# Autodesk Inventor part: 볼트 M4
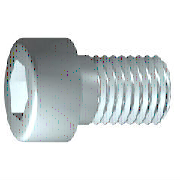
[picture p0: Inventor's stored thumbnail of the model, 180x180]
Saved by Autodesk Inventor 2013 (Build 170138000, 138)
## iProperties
IsCustomPart: 1
Created: 2015-10
Part Number: 볼트 M4
Material: 강, 연강
Description: 6각머리 태핑 나사
Document SubType Name: Modeling
Standard: KS B 1003
Designer: mdu
Standards Organization: KS
Language: ko-KR
Size Designation: M 4 x 16
Categories: <MemberInstance><Categories><Category DisplayName="조임쇠" InternalName="e4da775c-781d-43d5-af7c-5136215cf5a6" Mnemonic="FSTN"><Category DisplayName="볼트" InternalN
Density: 7.86 g/cm^3
Mass: 2.62973 g
Surface Area: 3.81118 cm^2
Volume: 0.334572 cm^3
Author: mdu
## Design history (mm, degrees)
sketch "스케치1"
  geometry: L1 (-1, 0)-(16, 0); L2 (16, 0)-(16, 2); L3 (16, 2)-(1.75, 2); L4 (1.75, 2)-(1.32, 2); L5 (1.32, 2)-(0, 2); L6 (0, 2)-(0, 3.5); L7 (0, 3.5)-(-4, 3.5); L8 (-4, 3.5)-(-4, 1.732); L9 (-4, 1.732)-(-2, 1.732); L10 (-2, 1.732)-(-1, 0); L11 (-8, 0)-(20, 0) reference; L12 (0, -0.7)-(0, 4.2) reference; L13 (1.75, 2)-(0, 2)
  constraints: 22 end point, 6 parallel, 2 collinear, 2 perpendicular, 1 horizontal, 1 point on line
  dimensions: "d1" = 14.25 distance from line of L3.end L2 (= GEL); "d2" = 0.42952 distance of L4.end L3.end (computed from GAL); "d3" = 4 distance between parallel lines of L8 L6 (= KOH); "d4" = 2 distance of L8.end L9.end (= INTI); "d5" = 60 deg angle of L10 L1; "d6" = 4 diameter of L3 L1 (= GD); "d7" = 4 diameter of L5 L1 (= BDM); "d8" = 3.4641 diameter of L9 L1 (= 1.1547 x SW); "d9" = 7 diameter of L7 L1 (= KOD); "d26" = 16 distance between parallel lines of L12 L2 (= NLG)
revolve "본체" sketch "스케치1" stored, may be unused: angle "d10" = 90 deg
sketch "스케치2"
  geometry: L1 (0, -4.9)-(0, 4.9) reference; L2 (-4.9, 0)-(4.9, 0) reference; L3 (1.732, 0)-(0.866, -1.5); L4 (0.866, -1.5)-(-0.866, -1.5); L5 (-0.866, -1.5)-(-1.732, 0); L6 (-1.732, 0)-(-0.866, 1.5); L7 (-0.866, 1.5)-(0.866, 1.5); L8 (0.866, 1.5)-(1.732, 0); 2 further points
  constraints: 12 end point, 1 coincident, 1 horizontal alignment, 1 point on line, 12 other
extrude "슬롯" join sketch "스케치2" stored distance "d11" = 10; taper "d12" = 0 deg
workplane "Work Plane1"
fillet "Fillet2" dims "d30" = 0.1 (= R)
body "Solid1"
fillet "모깎기1" dims "d17" = 0.4 (= RR)
feature "스레드" dims "d13" = 14.25 (= GEL), "d14" = 0
chamfer "모따기1" distance "d15" = 0.42941 (= -0.5 x SPD + 0.5 x GD); stored, may be unused: second distance "d16" = 0.42941 (= GUL), angle "d27" = 45 deg
other parameters: "GD" = 4 (= NND) [user parameter; used in 2 equation terms], "NLG" = 16 [user parameter; used in 1 equation term], "GEL" = 14.25 [user parameter; used in 2 equation terms], "KOD" = 7 [user parameter; used in 1 equation term], "KOH" = 4 [user parameter; used in 1 equation term], "INTI" = 2 [user parameter; used in 1 equation term], "GAL" = 0.42941 (= 0.61345 x PTC) [user parameter; used in 1 equation term], "GUL" = 0.42941 (= 0.61345 x PTC) [user parameter; used in 1 equation term], "BDM" = 4 (= NND) [user parameter; used in 1 equation term], "SW" = 3 [user parameter; used in 2 equation terms], "RR" = 0.4 [user parameter; used in 1 equation term], "SPD" = 3.14117 (= NND - 1.2269 x PTC) [user parameter; used in 1 equation term], "d19" = 0, "d28" = 0, "d29" = 0, "R" = 0.1 [user parameter; used in 1 equation term], "PHH" = 0.2 [user parameter], "GD1" = 3.14117 (= THREADDIA - 1.2269 x PTC) [user parameter], "THREADDIA" = 4 [user parameter; used in 1 equation term], "FAWI" = 45 deg [user parameter], "TPU" = 14.28571 (computed from PTC) [user parameter], "PTC" = 0.7 [user parameter; used in 5 equation terms], "NND" = 4 [user parameter; used in 3 equation terms], "TOA" = 30 deg [user parameter], "E0" = 3.465 (= 1.155 x SW) [user parameter]
